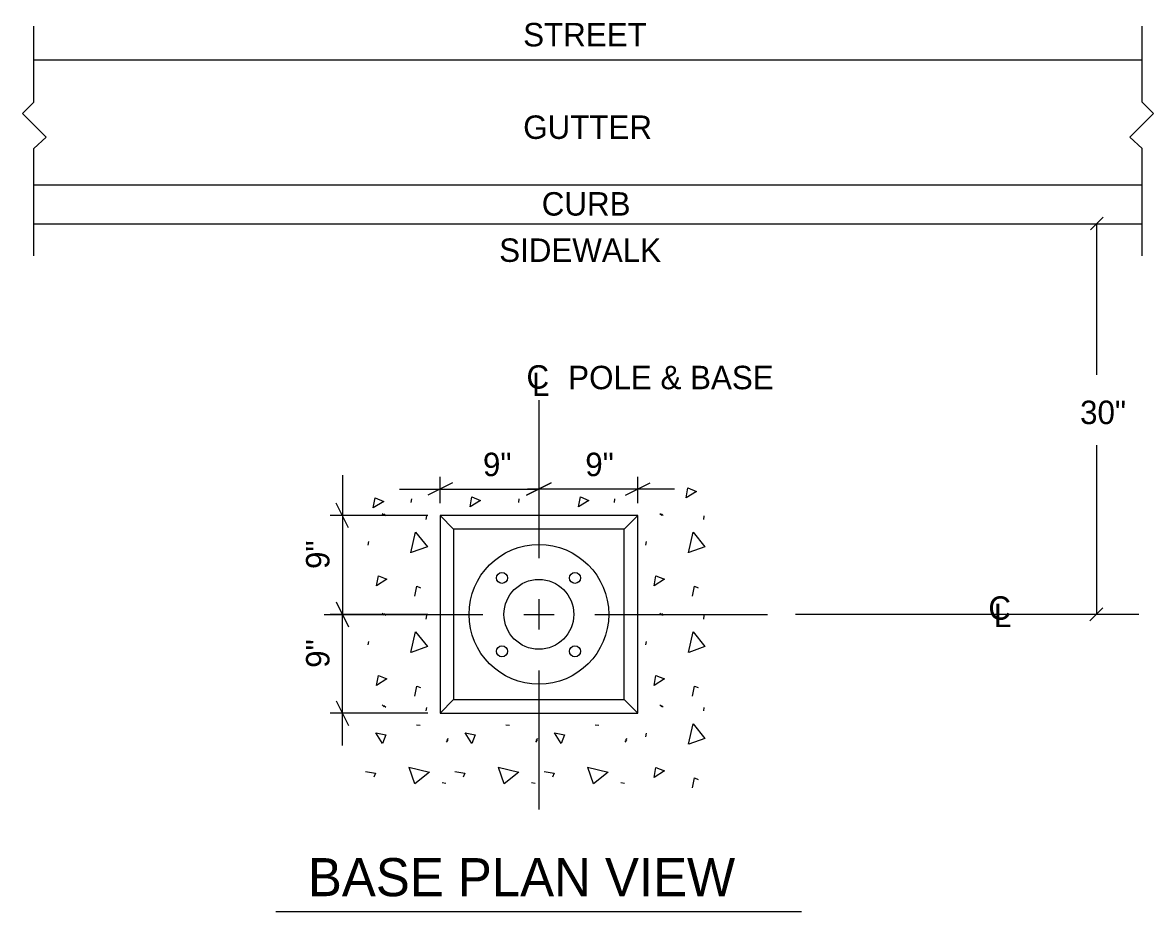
# Model space of a CAD drawing. Extents: x 10233.9 to 10280.1, y 10095.8 to 10159.3.
# Drawn here: x 10241.63 to 10273.81, y 10133.97 to 10159.26 of the extents above; entities that cross this region are included whole.
import ezdxf

# ---------------------------------------------------------------- set-up
doc = ezdxf.new("R2010")
doc.units = 0
for name, color, linetype in [('G-ANNO-TEXT', 7, 'Continuous'), ('G-DETL-LINE', 7, 'Continuous'), ('G-DETL-OTLN', 7, 'Continuous'), ('G-DETL-PATT', 7, 'Continuous')]:
    doc.layers.add(name, color=color, linetype=linetype)

msp = doc.modelspace()

# ---------------------------------------------------------------- linework, layer by layer
at = {"layer": 'G-ANNO-TEXT'}
for p, q in [((10241.955, 10156.994), (10241.955, 10159.159)), ((10273.49, 10156.994), (10273.49, 10159.159)), ((10241.955, 10156.994), (10241.632, 10156.671)), ((10273.49, 10156.994), (10273.813, 10156.671)), ((10241.632, 10156.671), (10242.298, 10156.004)), ((10273.813, 10156.671), (10273.147, 10156.004)), ((10242.298, 10156.004), (10241.955, 10155.674)), ((10273.147, 10156.004), (10273.49, 10155.674)), ((10241.955, 10152.622), (10241.955, 10155.674)), ((10273.49, 10152.622), (10273.49, 10155.674)), ((10272.386, 10153.727), (10272.019, 10153.359)), ((10272.197, 10153.535), (10272.197, 10149.239)), ((10256.325, 10148.514), (10256.325, 10144.018)), ((10272.197, 10147.235), (10272.197, 10142.422)), ((10250.733, 10146.388), (10250.733, 10142.424)), ((10253.864, 10146.162), (10253.161, 10145.811)), ((10253.513, 10145.588), (10253.513, 10146.338)), ((10255.974, 10145.811), (10256.677, 10146.162)), ((10256.677, 10146.162), (10255.974, 10145.811)), ((10258.786, 10145.811), (10259.489, 10146.162)), ((10259.138, 10145.588), (10259.138, 10146.338)), ((10250.733, 10146.102), (10250.733, 10144.007)), ((10252.361, 10145.986), (10256.325, 10145.986)), ((10252.927, 10145.986), (10253.513, 10145.986)), ((10256.716, 10145.986), (10255.998, 10145.986)), ((10260.186, 10145.986), (10256.118, 10145.986)), ((10250.909, 10144.885), (10250.558, 10145.588)), ((10253.161, 10145.237), (10250.382, 10145.237)), ((10250.558, 10142.776), (10250.909, 10142.072)), ((10256.325, 10142.855), (10256.325, 10141.993)), ((10272.375, 10142.611), (10272.008, 10142.243)), ((10250.218, 10142.424), (10254.731, 10142.424)), ((10253.161, 10142.424), (10250.382, 10142.424)), ((10250.733, 10139.498), (10250.733, 10142.424)), ((10255.894, 10142.424), (10256.756, 10142.424)), ((10257.919, 10142.424), (10262.835, 10142.424)), ((10273.398, 10142.422), (10263.628, 10142.422)), ((10256.325, 10140.83), (10256.325, 10136.873)), ((10250.558, 10139.963), (10250.909, 10139.26)), ((10253.161, 10139.612), (10250.382, 10139.612)), ((10250.733, 10138.691), (10250.733, 10139.612)), ((10248.834, 10133.973), (10263.796, 10133.973))]:
    msp.add_line(p, q, dxfattribs=at)
at = {"layer": 'G-DETL-LINE'}
for p, q in [((10241.955, 10158.198), (10273.493, 10158.198)), ((10241.955, 10154.641), (10273.493, 10154.641)), ((10241.955, 10153.535), (10273.493, 10153.535))]:
    msp.add_line(p, q, dxfattribs=at)
at = {"layer": 'G-DETL-OTLN'}
for p, q in [((10259.138, 10145.237), (10253.513, 10145.237)), ((10253.513, 10145.237), (10253.513, 10139.612)), ((10253.513, 10145.237), (10253.898, 10144.851)), ((10258.751, 10144.851), (10259.138, 10145.237)), ((10259.138, 10139.612), (10259.138, 10145.237)), ((10258.751, 10144.851), (10253.898, 10144.851)), ((10253.898, 10144.851), (10253.898, 10139.998)), ((10258.751, 10139.998), (10258.751, 10144.851)), ((10253.513, 10139.612), (10253.898, 10139.998)), ((10253.898, 10139.998), (10258.751, 10139.998)), ((10258.751, 10139.998), (10259.138, 10139.612)), ((10253.513, 10139.612), (10259.138, 10139.612))]:
    msp.add_line(p, q, dxfattribs=at)
for centre, radius in [((10256.325, 10142.424), 1.987), ((10255.274, 10143.46), 0.156), ((10257.352, 10143.46), 0.156), ((10256.325, 10142.424), 0.994), ((10255.274, 10141.373), 0.156), ((10257.352, 10141.373), 0.156)]:
    msp.add_circle(centre, radius, dxfattribs=at)
at = {"layer": 'G-DETL-PATT'}
for p, q in [((10252.693, 10145.607), (10252.709, 10145.708)), ((10255.75, 10145.607), (10255.766, 10145.708)), ((10258.475, 10145.607), (10258.49, 10145.708)), ((10251.864, 10145.296), (10251.92, 10145.246)), ((10251.91, 10145.283), (10251.966, 10145.234)), ((10253.117, 10145.124), (10253.133, 10145.226)), ((10259.763, 10145.296), (10259.82, 10145.246)), ((10259.81, 10145.283), (10259.866, 10145.234)), ((10261.017, 10145.124), (10261.033, 10145.226)), ((10251.47, 10144.392), (10251.486, 10144.493)), ((10259.37, 10144.392), (10259.386, 10144.493)), ((10251.864, 10142.457), (10251.92, 10142.407)), ((10251.91, 10142.445), (10251.966, 10142.395)), ((10253.117, 10142.286), (10253.133, 10142.387)), ((10259.763, 10142.457), (10259.82, 10142.407)), ((10259.81, 10142.445), (10259.866, 10142.395)), ((10261.017, 10142.286), (10261.033, 10142.387)), ((10251.47, 10141.553), (10251.486, 10141.654)), ((10259.37, 10141.553), (10259.386, 10141.654)), ((10251.864, 10139.845), (10251.92, 10139.795)), ((10251.91, 10139.833), (10251.966, 10139.783)), ((10253.117, 10139.674), (10253.133, 10139.775)), ((10259.763, 10139.845), (10259.82, 10139.795)), ((10259.81, 10139.833), (10259.866, 10139.783)), ((10261.017, 10139.674), (10261.033, 10139.775)), ((10252.841, 10139.283), (10252.942, 10139.267)), ((10255.383, 10139.283), (10255.485, 10139.267)), ((10257.926, 10139.283), (10258.027, 10139.267)), ((10259.37, 10138.941), (10259.386, 10139.042)), ((10253.733, 10138.843), (10253.683, 10138.787)), ((10253.745, 10138.889), (10253.696, 10138.833)), ((10256.275, 10138.843), (10256.226, 10138.787)), ((10256.287, 10138.889), (10256.238, 10138.833)), ((10258.818, 10138.843), (10258.768, 10138.787)), ((10258.83, 10138.889), (10258.78, 10138.833)), ((10253.574, 10137.636), (10253.675, 10137.62)), ((10256.116, 10137.636), (10256.218, 10137.62)), ((10258.659, 10137.636), (10258.76, 10137.62))]:
    msp.add_line(p, q, dxfattribs=at)
for points in [[(10260.512, 10145.735), (10260.565, 10146.019), (10260.807, 10145.922), (10260.512, 10145.735)], [(10251.613, 10145.451), (10251.667, 10145.735), (10251.908, 10145.638), (10251.613, 10145.451)], [(10254.368, 10145.48), (10254.421, 10145.763), (10254.662, 10145.666), (10254.368, 10145.48)], [(10257.455, 10145.48), (10257.508, 10145.763), (10257.75, 10145.666), (10257.455, 10145.48)], [(10252.681, 10144.177), (10252.814, 10144.763), (10253.152, 10144.347), (10252.691, 10144.18)], [(10260.58, 10144.177), (10260.714, 10144.763), (10261.052, 10144.347), (10260.59, 10144.18)], [(10251.704, 10143.237), (10251.757, 10143.521), (10251.999, 10143.424), (10251.704, 10143.237)], [(10252.799, 10142.938), (10252.852, 10143.222), (10252.96, 10143.179)], [(10259.604, 10143.237), (10259.657, 10143.521), (10259.899, 10143.424), (10259.604, 10143.237)], [(10260.698, 10142.938), (10260.752, 10143.222), (10260.86, 10143.179)], [(10252.681, 10141.338), (10252.814, 10141.924), (10253.152, 10141.508), (10252.691, 10141.341)], [(10260.58, 10141.338), (10260.714, 10141.924), (10261.052, 10141.508), (10260.59, 10141.341)], [(10251.704, 10140.398), (10251.757, 10140.682), (10251.999, 10140.585), (10251.704, 10140.398)], [(10259.604, 10140.398), (10259.657, 10140.682), (10259.899, 10140.585), (10259.604, 10140.398)], [(10252.799, 10140.099), (10252.852, 10140.383), (10252.96, 10140.34)], [(10260.698, 10140.099), (10260.752, 10140.383), (10260.86, 10140.34)], [(10251.686, 10139.049), (10251.97, 10138.995), (10251.873, 10138.754), (10251.686, 10139.049)], [(10254.229, 10139.049), (10254.512, 10138.995), (10254.415, 10138.754), (10254.229, 10139.049)], [(10256.771, 10139.049), (10257.055, 10138.995), (10256.958, 10138.754), (10256.771, 10139.049)], [(10260.58, 10138.727), (10260.714, 10139.312), (10261.052, 10138.896), (10260.59, 10138.729)], [(10252.627, 10138.072), (10253.212, 10137.938), (10252.796, 10137.601), (10252.629, 10138.062)], [(10255.169, 10138.072), (10255.754, 10137.938), (10255.339, 10137.601), (10255.172, 10138.062)], [(10257.712, 10138.072), (10258.297, 10137.938), (10257.881, 10137.601), (10257.714, 10138.062)], [(10259.604, 10137.786), (10259.657, 10138.07), (10259.899, 10137.973), (10259.604, 10137.786)], [(10251.388, 10137.954), (10251.671, 10137.901), (10251.628, 10137.793)], [(10253.93, 10137.954), (10254.214, 10137.901), (10254.17, 10137.793)], [(10256.473, 10137.954), (10256.756, 10137.901), (10256.713, 10137.793)], [(10260.698, 10137.488), (10260.752, 10137.771), (10260.86, 10137.728)]]:
    msp.add_lwpolyline(points, dxfattribs=at)

# ---------------------------------------------------------------- texts
at = {"layer": 'G-ANNO-TEXT'}
for s, height, p in [('STREET', 0.6667, (10255.878, 10158.583)), ('GUTTER', 0.6667, (10255.878, 10155.951)), ('CURB', 0.6667, (10256.406, 10153.769)), ('SIDEWALK', 0.6667, (10255.195, 10152.452)), ('C', 0.667, (10255.971, 10148.845)), ('POLE & BASE', 0.66667, (10257.159, 10148.829)), ('L', 0.667, (10256.127, 10148.636)), ('30"', 0.6667, (10271.726, 10147.837)), ('9"', 0.6667, (10254.733, 10146.356)), ('9"', 0.6667, (10257.645, 10146.356)), ('C', 0.667, (10269.117, 10142.269)), ('L', 0.667, (10269.272, 10142.06)), ('BASE PLAN VIEW', 1.08333, (10249.752, 10134.405))]:
    msp.add_text(s, height=height, dxfattribs=at).set_placement(p)
for p in [(10250.364, 10143.714), (10250.364, 10140.902)]:
    msp.add_text('9"', height=0.6667, rotation=90, dxfattribs=at).set_placement(p)

doc.saveas('drawing.dxf')
